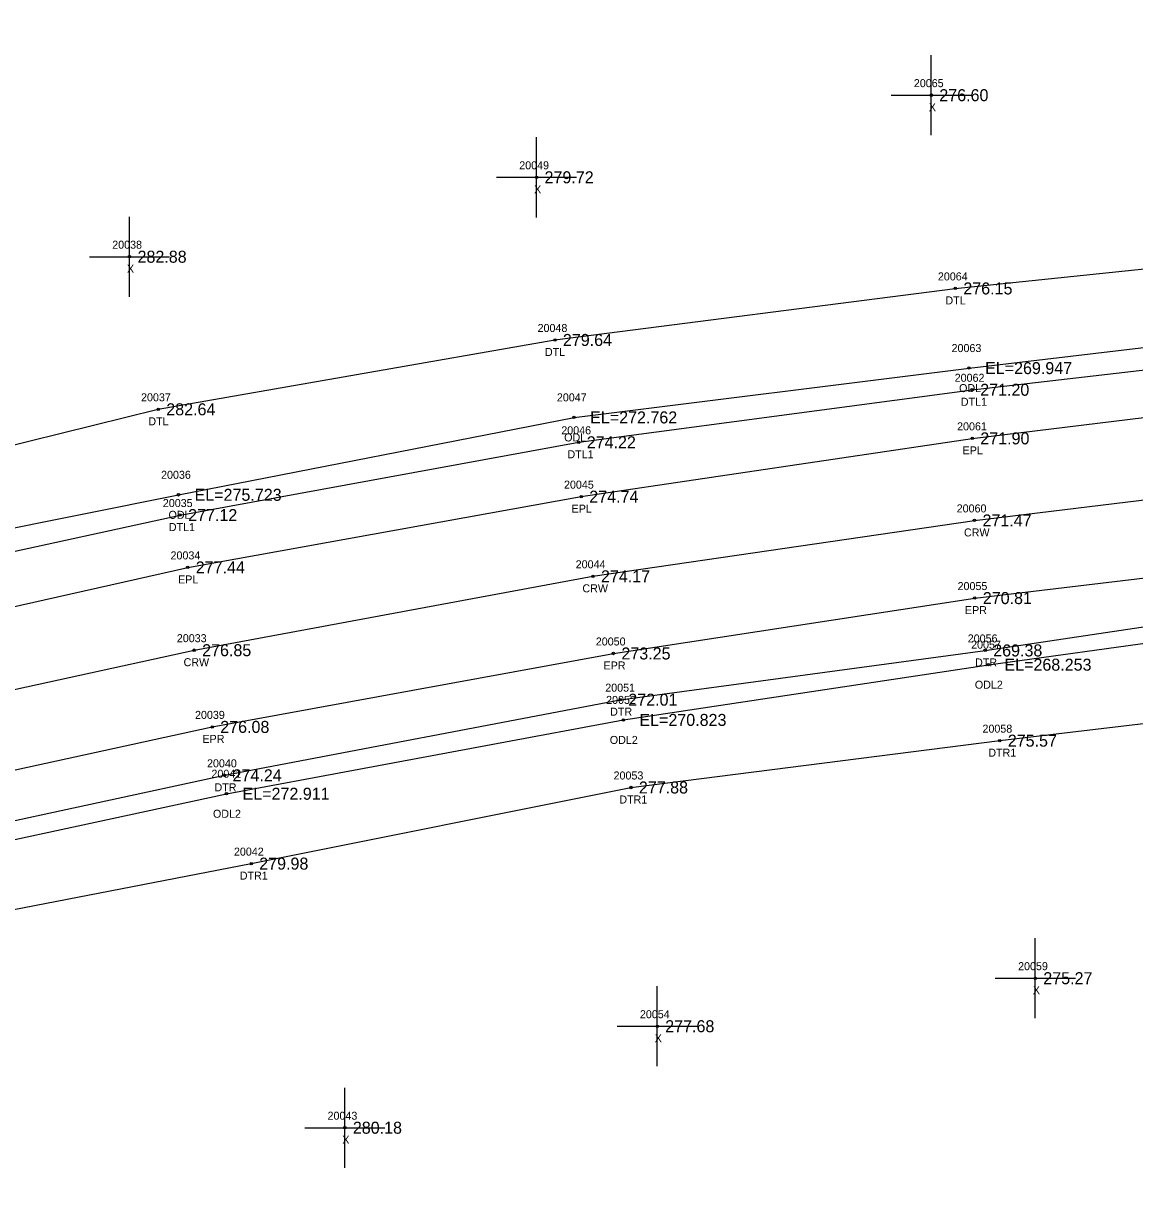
# Model space of a CAD drawing. Extents: x 2275563 to 2277161, y 1075719 to 1076412.
# Drawn here: x 2275701.9 to 2275840.8, y 1075932.2 to 1076077 of the extents above; entities that cross this region are included whole.
import ezdxf

# ---------------------------------------------------------------- set-up
doc = ezdxf.new("R2010")
doc.units = 0
for name, color, linetype in [('RD_DTM_BkLn1', 7, 'Continuous'), ('RD_EX_H2O', 7, 'Continuous'), ('RD_EX_H2O_txCode', 7, 'Continuous'), ('RD_EX_Misc', 7, 'Continuous'), ('RD_EX_Misc_txCode', 7, 'Continuous'), ('RD_EX_Road', 7, 'Continuous'), ('RD_EX_Road_txCode', 7, 'Continuous'), ('RD_EX_TX_H2O_ELEV', 7, 'Continuous'), ('RD_EX_TX_Misc_ELEV', 7, 'Continuous'), ('RD_EX_TX_Road_ELEV', 7, 'Continuous'), ('RD_HC_Survey_ELEV', 7, 'Continuous'), ('RD_HC_Survey_txCode', 7, 'Continuous'), ('RD_SMD_Locator', 7, 'Continuous')]:
    doc.layers.add(name, color=color, linetype=linetype)

msp = doc.modelspace()

# ---------------------------------------------------------------- linework, layer by layer
at = {"layer": 'RD_DTM_BkLn1'}
msp.add_lwpolyline([(2275581.11, 1075960.98), (2275628.56, 1075975.85), (2275676.42, 1075988.42), (2275723.3, 1075998.64), (2275773.11, 1076007.87), (2275820.75, 1076014.85), (2275866.6, 1076020.4), (2275966.91, 1076031.19), (2276055.16, 1076040.4), (2276149.88, 1076050.18), (2276235.38, 1076058.41), (2276319.71, 1076067.21)], dxfattribs=at)
at = {"layer": 'RD_EX_H2O'}
for points in [[(2275571.65, 1075989.72), (2275621.14, 1076003.61), (2275670.33, 1076016.76), (2275718.82, 1076028.73), (2275768.35, 1076037.39), (2275818.36, 1076043.83), (2275863.99, 1076048.58), (2275939.76, 1076056.32), (2275942.53, 1076068.3)], [(2275576.42, 1075977.43), (2275624.64, 1075992.17), (2275672.66, 1076004.86), (2275721.55, 1076015.52), (2275771.33, 1076024.61), (2275820.46, 1076031.17), (2275865.41, 1076036.37), (2275943.27, 1076044.07), (2275943.38, 1076052.27), (2275942.53, 1076068.3)], [(2275575.79, 1075980.11), (2275624.24, 1075995.2), (2275672.15, 1076008.16), (2275721.35, 1076018.05), (2275770.75, 1076027.72), (2275820.07, 1076033.88), (2275865.07, 1076039.19), (2275940.33, 1076048.37)], [(2275584.42, 1075945.55), (2275630.75, 1075959.99), (2275679.72, 1075972.8), (2275727.1, 1075983.01), (2275776.52, 1075992.46), (2275822.09, 1075998.61), (2275868.31, 1076005.5), (2275971.07, 1076013.85), (2276058.03, 1076018.84), (2276110, 1076025.4), (2276114.25, 1076022.31), (2276152.59, 1076021.64), (2276188.46, 1076022.22), (2276200.36, 1076021.35), (2276207.63, 1076015.4), (2276245.53, 1076014.24), (2276263.41, 1076017.81), (2276276.57, 1076007.97), (2276280.95, 1075989.03), (2276329.97, 1075967.39)], [(2275584.66, 1075942.4), (2275631.99, 1075956.6), (2275680.23, 1075970.55), (2275727.34, 1075980.71), (2275776.9, 1075989.93), (2275822.49, 1075996.83), (2275868.2, 1076003.14), (2275971.77, 1076011.3), (2276058.74, 1076015.62), (2276117.31, 1076020.2), (2276152.71, 1076018.31), (2276188.2, 1076020.3), (2276200.59, 1076018.25), (2276207.46, 1076011.88), (2276246.17, 1076010.02), (2276264.15, 1076012.48), (2276274.37, 1076006.56), (2276276.43, 1075986.9), (2276334.04, 1075961.68)], [(2275587.87, 1075932.23), (2275632.3, 1075945.74), (2275680.34, 1075962.3), (2275730.43, 1075971.98), (2275777.84, 1075981.49), (2275823.91, 1075987.34), (2275869.26, 1075992.75), (2275941.88, 1076000), (2275968.29, 1076005.71), (2275973.41, 1076009.09), (2276058.49, 1076013.63), (2276114.54, 1076018.47), (2276125.61, 1076012.99), (2276153.29, 1076014.06), (2276186.69, 1076017.67), (2276196.76, 1076016.05), (2276210.13, 1076008.45), (2276246.2, 1076005.42), (2276264.34, 1076010.6), (2276271.38, 1076006), (2276275.05, 1075983.37), (2276331.39, 1075956.06)]]:
    msp.add_lwpolyline(points, dxfattribs=at)
at = {"layer": 'RD_EX_Misc'}
for p, q in [((2275815.36, 1076062.97), (2275815.36, 1076072.97)), ((2275810.36, 1076067.97), (2275820.36, 1076067.97)), ((2275766.06, 1076052.71), (2275766.06, 1076062.71)), ((2275761.06, 1076057.71), (2275771.06, 1076057.71)), ((2275715.23, 1076042.79), (2275715.23, 1076052.79)), ((2275710.23, 1076047.79), (2275720.23, 1076047.79)), ((2275828.35, 1075952.67), (2275828.35, 1075962.67)), ((2275781.13, 1075946.67), (2275781.13, 1075956.67)), ((2275823.35, 1075957.67), (2275833.35, 1075957.67)), ((2275776.13, 1075951.67), (2275786.13, 1075951.67)), ((2275742.12, 1075933.99), (2275742.12, 1075943.99)), ((2275737.12, 1075938.99), (2275747.12, 1075938.99))]:
    msp.add_line(p, q, dxfattribs=at)
at = {"layer": 'RD_EX_Road'}
for points in [[(2275577.73, 1075970.55), (2275625.95, 1075985.49), (2275674.01, 1075998.04), (2275722.5, 1076008.98), (2275771.65, 1076017.82), (2275820.48, 1076025.1), (2275865.7, 1076030.61), (2275949.17, 1076039.36), (2275965.19, 1076041.07), (2276054.28, 1076050.49), (2276149.42, 1076060.39), (2276235.13, 1076068.68), (2276318.87, 1076076.96)], [(2275583.24, 1075951.04), (2275629.66, 1075965.93), (2275678.06, 1075978.68), (2275725.56, 1075989.06), (2275775.66, 1075998.23), (2275820.79, 1076005.15), (2275867.87, 1076010.76), (2275970.82, 1076021.78), (2276056.64, 1076030.61), (2276150.8, 1076040.39), (2276237.04, 1076048.76), (2276320.71, 1076057.95)]]:
    msp.add_lwpolyline(points, dxfattribs=at)
at = {"layer": 'RD_SMD_Locator'}
for centre in [(2275815.36, 1076067.97), (2275766.06, 1076057.71), (2275715.23, 1076047.79), (2275818.36, 1076043.83), (2275768.35, 1076037.39), (2275820.07, 1076033.88), (2275820.46, 1076031.17), (2275718.82, 1076028.73), (2275770.75, 1076027.72), (2275771.33, 1076024.61), (2275820.48, 1076025.1), (2275721.35, 1076018.05), (2275771.65, 1076017.82), (2275721.55, 1076015.52), (2275820.75, 1076014.85), (2275722.5, 1076008.98), (2275773.11, 1076007.87), (2275820.79, 1076005.15), (2275723.3, 1075998.64), (2275775.66, 1075998.23), (2275822.09, 1075998.61), (2275822.49, 1075996.83), (2275776.52, 1075992.46), (2275776.9, 1075989.93), (2275725.56, 1075989.06), (2275823.91, 1075987.34), (2275727.1, 1075983.01), (2275777.84, 1075981.49), (2275727.34, 1075980.71), (2275730.43, 1075971.98), (2275828.35, 1075957.67), (2275781.13, 1075951.67), (2275742.12, 1075938.99)]:
    msp.add_circle(centre, 0.15, dxfattribs=at)

# ---------------------------------------------------------------- texts
at = {"layer": 'RD_EX_H2O_txCode'}
for s, p in [('20064', (2275816.18, 1076044.83)), ('DTL', (2275817.12, 1076041.83)), ('20048', (2275766.19, 1076038.39)), ('DTL', (2275767.11, 1076035.39)), ('20063', (2275817.89, 1076035.88)), ('20062', (2275818.28, 1076032.17)), ('ODL', (2275818.83, 1076030.88)), ('20037', (2275716.67, 1076029.73)), ('20047', (2275768.6, 1076029.72)), ('DTL1', (2275819.05, 1076029.17)), ('DTL', (2275717.58, 1076026.73)), ('20046', (2275769.15, 1076025.61)), ('ODL', (2275769.51, 1076024.72)), ('DTL1', (2275769.92, 1076022.61)), ('20036', (2275719.17, 1076020.05)), ('20035', (2275719.39, 1076016.52)), ('ODL', (2275720.1, 1076015.05)), ('DTL1', (2275720.14, 1076013.52)), ('20056', (2275819.91, 1075999.61)), ('20057', (2275820.33, 1075998.83)), ('DTR', (2275820.82, 1075996.61)), ('20051', (2275774.64, 1075993.46)), ('ODL2', (2275820.8, 1075993.83)), ('20052', (2275774.75, 1075991.93)), ('DTR', (2275775.25, 1075990.46)), ('20058', (2275821.75, 1075988.34)), ('ODL2', (2275775.21, 1075986.93)), ('DTR1', (2275822.48, 1075985.34)), ('20040', (2275724.91, 1075984.01)), ('20041', (2275725.46, 1075982.71)), ('20053', (2275775.68, 1075982.49)), ('DTR', (2275725.84, 1075981.01)), ('DTR1', (2275776.4, 1075979.49)), ('ODL2', (2275725.65, 1075977.71)), ('20042', (2275728.27, 1075972.98)), ('DTR1', (2275729, 1075969.98))]:
    msp.add_text(s, height=1, dxfattribs=at).set_placement(p)
at = {"layer": 'RD_EX_Misc_txCode'}
for s, p in [('20065', (2275813.18, 1076068.97)), ('X', (2275815.05, 1076065.97)), ('20049', (2275763.9, 1076058.71)), ('X', (2275765.75, 1076055.71)), ('20038', (2275713.07, 1076048.79)), ('X', (2275714.91, 1076045.79)), ('20059', (2275826.2, 1075958.67)), ('X', (2275828.04, 1075955.67)), ('20054', (2275778.97, 1075952.67)), ('X', (2275780.82, 1075949.67)), ('20043', (2275739.96, 1075939.99)), ('X', (2275741.8, 1075936.99))]:
    msp.add_text(s, height=1, dxfattribs=at).set_placement(p)
at = {"layer": 'RD_EX_Road_txCode'}
for s, p in [('20061', (2275818.58, 1076026.1)), ('EPL', (2275819.27, 1076023.1)), ('20045', (2275769.49, 1076018.82)), ('EPL', (2275770.44, 1076015.82)), ('20034', (2275720.35, 1076009.98)), ('EPL', (2275721.3, 1076006.98)), ('20055', (2275818.64, 1076006.15)), ('EPR', (2275819.56, 1076003.15)), ('20050', (2275773.46, 1075999.23)), ('EPR', (2275774.43, 1075996.23)), ('20039', (2275723.41, 1075990.06)), ('EPR', (2275724.34, 1075987.06))]:
    msp.add_text(s, height=1, dxfattribs=at).set_placement(p)
at = {"layer": 'RD_EX_TX_H2O_ELEV'}
for s, p in [('276.15', (2275819.36, 1076043.08)), ('279.64', (2275769.35, 1076036.64)), ('EL=269.947', (2275822.07, 1076033.13)), ('271.20', (2275821.46, 1076030.42)), ('282.64', (2275719.82, 1076027.98)), ('EL=272.762', (2275772.75, 1076026.97)), ('274.22', (2275772.33, 1076023.86)), ('EL=275.723', (2275723.35, 1076017.3)), ('277.12', (2275722.55, 1076014.77)), ('269.38', (2275823.09, 1075997.86)), ('EL=268.253', (2275824.49, 1075996.08)), ('272.01', (2275777.52, 1075991.71)), ('EL=270.823', (2275778.9, 1075989.18)), ('275.57', (2275824.91, 1075986.59)), ('274.24', (2275728.1, 1075982.26)), ('EL=272.911', (2275729.34, 1075979.96)), ('277.88', (2275778.84, 1075980.74)), ('279.98', (2275731.43, 1075971.23))]:
    msp.add_text(s, height=1.5, dxfattribs=at).set_placement(p)
at = {"layer": 'RD_EX_TX_Misc_ELEV'}
for s, p in [('276.60', (2275816.36, 1076067.22)), ('279.72', (2275767.06, 1076056.96)), ('282.88', (2275716.23, 1076047.04)), ('275.27', (2275829.35, 1075956.92)), ('277.68', (2275782.13, 1075950.92)), ('280.18', (2275743.12, 1075938.24))]:
    msp.add_text(s, height=1.5, dxfattribs=at).set_placement(p)
at = {"layer": 'RD_EX_TX_Road_ELEV'}
for s, p in [('271.90', (2275821.48, 1076024.35)), ('274.74', (2275772.65, 1076017.07)), ('277.44', (2275723.5, 1076008.23)), ('270.81', (2275821.79, 1076004.4)), ('273.25', (2275776.66, 1075997.48)), ('276.08', (2275726.56, 1075988.31))]:
    msp.add_text(s, height=1.5, dxfattribs=at).set_placement(p)
at = {"layer": 'RD_HC_Survey_ELEV'}
for s, p in [('271.47', (2275821.75, 1076014.1)), ('274.17', (2275774.11, 1076007.12)), ('276.85', (2275724.3, 1075997.89))]:
    msp.add_text(s, height=1.5, dxfattribs=at).set_placement(p)
at = {"layer": 'RD_HC_Survey_txCode'}
for s, p in [('20060', (2275818.53, 1076015.85)), ('CRW', (2275819.44, 1076012.85)), ('20044', (2275770.95, 1076008.87)), ('CRW', (2275771.79, 1076005.87)), ('20033', (2275721.14, 1075999.64)), ('CRW', (2275721.98, 1075996.64))]:
    msp.add_text(s, height=1, dxfattribs=at).set_placement(p)

doc.saveas('drawing.dxf')
